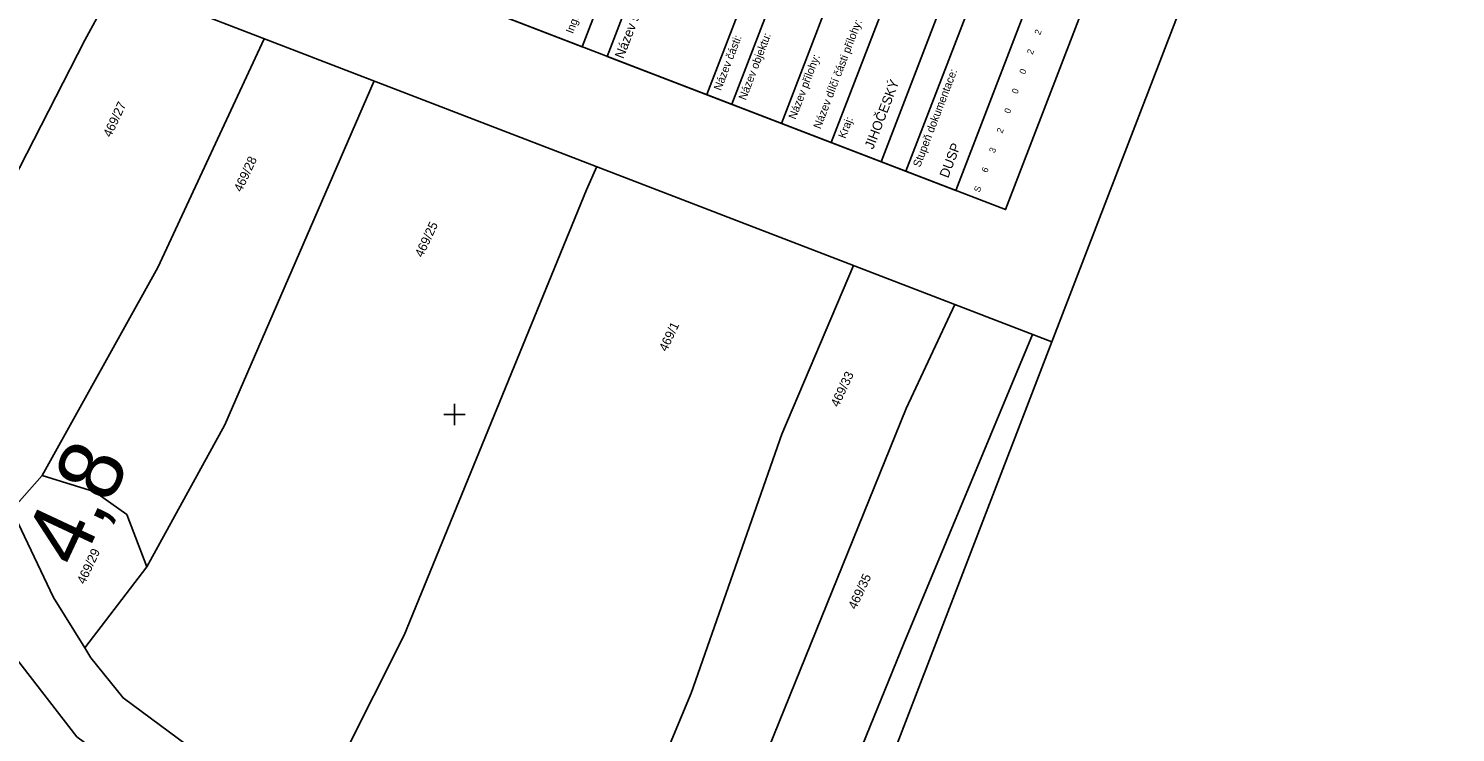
# Model space of a CAD drawing. Extents: x -755344 to -754412, y -1162670 to -1161477.
# Drawn here: x -754679.8 to -754412.4, y -1161959.6 to -1161827.7 of the extents above; entities that cross this region are included whole.
import ezdxf

# ---------------------------------------------------------------- set-up
doc = ezdxf.new("R2010")
doc.units = 0
for name, color, linetype in [('Formát', 7, 'Continuous'), ('Katastrální hranice', 7, 'Continuous'), ('SO 11-10-01_popisove_pole', 7, 'Continuous'), ('Staniceni a namezniky', 7, 'Continuous'), ('Síť', 7, 'Continuous'), ('Tabulka', 7, 'Continuous'), ('Vrstva 55', 7, 'Continuous'), ('Vrstva 57', 7, 'Continuous')]:
    doc.layers.add(name, color=color, linetype=linetype)

msp = doc.modelspace()

# ---------------------------------------------------------------- linework, layer by layer
at = {"layer": 'Formát'}
msp.add_line((-754488.01, -1161886.37), (-754412.37, -1161689.85), dxfattribs=at)
msp.add_lwpolyline([(-754488.01, -1161886.37), (-754789.71, -1162670.32), (-755344.08, -1162456.97), (-755042.37, -1161673.02)], close=True, dxfattribs=at)
for points in [[(-755344.08, -1162456.97), (-754789.71, -1162670.32), (-754488.01, -1161886.37), (-755042.37, -1161673.02)], [(-755344.08, -1162456.97), (-754789.71, -1162670.32), (-754488.01, -1161886.37), (-755042.37, -1161673.02)], [(-754789.71, -1162670.32), (-754488.01, -1161886.37), (-755042.37, -1161673.02), (-755344.08, -1162456.97)]]:
    msp.add_lwpolyline(points, dxfattribs=at)
at = {"layer": 'Katastrální hranice'}
msp.add_line((-754682.93, -1161917.84), (-754675.16, -1161934.28), dxfattribs=at)
at = {"layer": 'Síť'}
for points in [[(-754600, -1161898), (-754600, -1161900), (-754600, -1161902)], [(-754598, -1161900), (-754600, -1161900), (-754602, -1161900)]]:
    msp.add_lwpolyline(points, dxfattribs=at)
at = {"layer": 'Tabulka'}
for p, q in [((-754552.69, -1161840.05), (-754505.87, -1161718.4)), ((-754548.02, -1161841.85), (-754501.2, -1161720.2)), ((-754538.69, -1161845.44), (-754491.87, -1161723.79)), ((-754529.35, -1161849.03), (-754482.54, -1161727.38)), ((-754520.02, -1161852.62), (-754473.2, -1161730.97)), ((-754515.36, -1161854.42), (-754468.54, -1161732.77))]:
    msp.add_line(p, q, dxfattribs=at)
for points in [[(-754739.34, -1161768.22), (-754678.28, -1161609.56), (-754435.63, -1161702.95), (-754496.69, -1161861.6)], [(-754622.68, -1161813.11), (-754561.62, -1161654.46), (-754514.96, -1161672.42), (-754576.02, -1161831.07)], [(-754571.36, -1161832.88), (-754510.3, -1161674.22), (-754444.97, -1161699.37), (-754506.03, -1161858.02)]]:
    msp.add_lwpolyline(points, close=True, dxfattribs=at)
at = {"layer": 'Vrstva 55'}
for p, q in [((-754682.93, -1161917.84), (-754677.24, -1161911.45)), ((-754682.93, -1161917.84), (-754675.16, -1161934.28)), ((-754682.93, -1161917.84), (-754675.16, -1161934.28)), ((-754657.61, -1161928.54), (-754669.27, -1161943.74)), ((-754675.16, -1161934.28), (-754669.27, -1161943.74)), ((-754675.16, -1161934.28), (-754669.27, -1161943.74))]:
    msp.add_line(p, q, dxfattribs=at)
for points in [[(-754700.13, -1161883.31), (-754693.64, -1161874.43), (-754682.9, -1161856.46), (-754669.27, -1161829.84), (-754663.3, -1161818.91)], [(-754677.24, -1161911.45), (-754655.58, -1161872.43), (-754635.62, -1161829.56)], [(-754615.06, -1161837.48), (-754643, -1161901.95), (-754657.61, -1161928.54)], [(-754573.32, -1161853.54), (-754575.25, -1161857.88), (-754609.39, -1161941.34), (-754620.82, -1161964.09), (-754630.9, -1161973.72)], [(-754581.59, -1162005.57), (-754574.99, -1161995.43), (-754567.68, -1161981.15), (-754555.59, -1161952.23), (-754538.63, -1161903.69), (-754525.17, -1161872.07)], [(-754566.03, -1162015.68), (-754549.09, -1161982.12), (-754515.32, -1161898.89), (-754506.22, -1161879.36)], [(-754548.91, -1162026.6), (-754544.92, -1162019.1), (-754539.09, -1162000.11), (-754515.76, -1161942.9), (-754491.63, -1161884.98)], [(-754677.24, -1161911.45), (-754667.41, -1161914.5), (-754661.4, -1161918.76), (-754657.61, -1161928.54)], [(-754637.39, -1161984.8), (-754642.71, -1161981.11), (-754670.75, -1161960.4), (-754682.08, -1161945.77), (-754686.04, -1161937.95)], [(-754669.27, -1161943.74), (-754668.12, -1161945.6), (-754662.1, -1161953.11), (-754649.99, -1161962)], [(-754669.27, -1161943.74), (-754668.12, -1161945.6), (-754662.1, -1161953.11), (-754649.99, -1161962)]]:
    msp.add_lwpolyline(points, dxfattribs=at)

# ---------------------------------------------------------------- texts
at = {"layer": 'SO 11-10-01_popisove_pole'}
for s, p in [('2', (-754490.22, -1161828.96)), ('2', (-754491.63, -1161832.64)), ('0', (-754493.05, -1161836.33)), ('0', (-754494.47, -1161840.01)), ('0', (-754495.89, -1161843.7)), ('2', (-754497.31, -1161847.39)), ('3', (-754498.73, -1161851.07)), ('6', (-754500.15, -1161854.76)), ('S', (-754501.56, -1161858.45))]:
    msp.add_text(s, height=1.2, rotation=68.9507, dxfattribs=at).set_placement(p)
at = {"layer": 'Staniceni a namezniky'}
msp.add_text('4,8', height=12, rotation=64.9752, dxfattribs=at).set_placement((-754670.25, -1161929.14))
at = {"layer": 'Tabulka'}
for s, height, p in [('Název stavby/akce:', 1.8, (-754568.33, -1161833.44)), ('Ing. Vít Hoznour', 1.5, (-754577.79, -1161828.73)), ('Název dílčí části přílohy:', 1.5, (-754531.39, -1161846.59)), ('Název části:', 1.5, (-754550.05, -1161839.41)), ('Název objektu:', 1.5, (-754545.39, -1161841.2)), ('Název přílohy:', 1.5, (-754536.05, -1161844.8)), ('Stupeň dokumentace:', 1.5, (-754512.72, -1161853.77)), ('JIHOČESKÝ', 1.8, (-754521.5, -1161850.4)), ('Kraj:', 1.5, (-754526.72, -1161848.39)), ('DUSP', 1.8, (-754507.46, -1161855.8))]:
    msp.add_text(s, height=height, rotation=68.9507, dxfattribs=at).set_placement(p)
at = {"layer": 'Vrstva 57'}
for s, p in [('469/27', (-754664.38, -1161848.18)), ('469/28', (-754639.89, -1161858.42)), ('469/25', (-754605.96, -1161870.67)), ('469/1', (-754560.21, -1161888.31)), ('469/33', (-754528.03, -1161898.74)), ('469/29', (-754669.29, -1161931.93)), ('469/35', (-754524.75, -1161936.65))]:
    msp.add_text(s, height=1.7, rotation=65, dxfattribs=at).set_placement(p)

doc.saveas('drawing.dxf')
